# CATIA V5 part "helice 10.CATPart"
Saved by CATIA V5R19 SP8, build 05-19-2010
Part number: helice 10
Bounding box of the stored display mesh (mm): x -17.321 to 17.321, y -30 to 195, z -10 to 20
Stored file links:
  G:\EU_thinkMotion\CFAO_2010\MMS_groupe2\MMS_groupe2\A reprendre\splanchenault\Planchenault\helice 10.CATPart
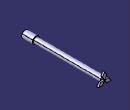
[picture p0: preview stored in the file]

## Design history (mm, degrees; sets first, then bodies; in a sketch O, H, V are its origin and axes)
Body1 (main body)
  Sketch1 on xy-plane, origin (0, 0, 0), H (1, 0, 0), V (0, 1, 0)
    line L1 (0, 0) -> (0, -30)
    line L2 (0, -30) -> (10, -30)
    line L3 (10, -30) -> (10, 0)
    line L4 (10, 0) -> (7.5, 0)
    line L5 (7.5, 0) -> (7.5, 190)
    line L6 (7.5, 190) -> (0, 190)
    point P6 (0, 190)
    line L7 (0, 190) -> (0, 0)
    length L6 = 7.5
    length L2 = 10
    length L7 = 190
    length L5 = 190
    length L3 = 30
    vertical: L1 V, L3 V, L5 V, L7 V
    horizontal: L2 H, L4 H, L6 H
    coincidence: P6 V
  Shaft1: profile Sketch1, axis Sketch1.L7, angle 360
  Sketch2 on face of Shaft1 from Sketch1.L6, origin (0, 190, 0), H (-1, 0, 0), V (0, 0, 1)
    construction line L1 (27.3861, -15.8114) -> (-27.3861, 15.8114)
    axis line L2 (-27.3861, -15.8114) -> (27.3861, 15.8114)
    line L3 (0, 0) -> (5.7735, 10)
    point P5 (5.7735, 10)
    line L4 (5.7735, 10) -> (0, 20)
    point P6 (0, 20)
    line L5 (0, 20) -> (-5.7735, 10)
    point P7 (-5.7735, 10)
    line L6 (-5.7735, 10) -> (0, 0)
    point P8 (-11.547, 0)
    point P9 (-17.3205, -10)
    line L7 (-17.3205, -10) -> (-11.547, 0)
    point P10 (-5.7735, -10)
    line L8 (-5.7735, -10) -> (-17.3205, -10)
    point P11 (0, 0)
    line L9 (0, 0) -> (-5.7735, -10)
    line L10 (-11.547, 0) -> (0, 0)
    point P12 (5.7735, -10)
    point P13 (17.3205, -10)
    line L11 (17.3205, -10) -> (5.7735, -10)
    point P14 (11.547, 0)
    line L12 (11.547, 0) -> (17.3205, -10)
    point P15 (0, 0)
    line L13 (0, 0) -> (11.547, 0)
    line L14 (5.7735, -10) -> (0, 0)
    angle L1 V = 60
    angle L2 V = 60
    perpendicularity: L3 L1, L4 L2
    parallelism: L5 L3
    symmetry: P7 P8 L1, P6 P9 L1, L5 L7 L1, P5 P10 L1, L4 L8 L1, O P11 L1, L3 L9 L1, L6 L10 L1, P7 P12 L2, P6 P13 L2, L5 L11 L2, P5 P14 L2, L4 L12 L2, O P15 L2, L3 L13 L2, L6 L14 L2
    coincidence: O P11, O P15, P11 P15
  Pad1: profile Sketch2, direction (0, 1, 0), length 5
